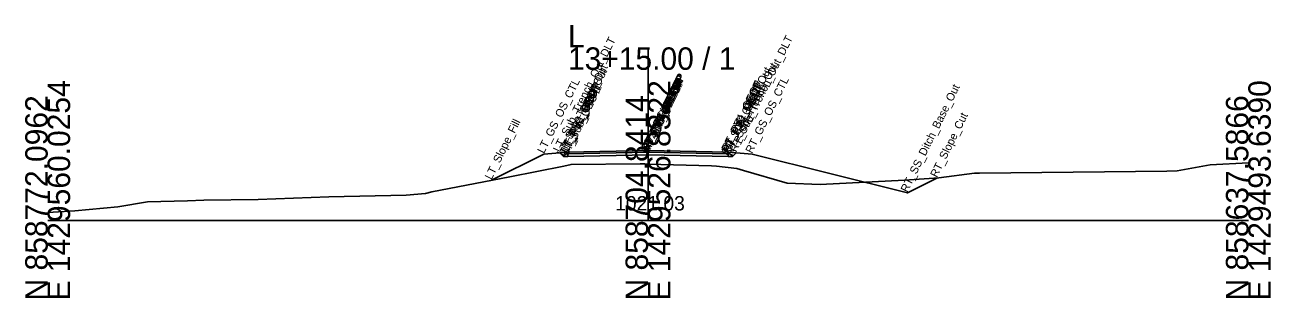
# Model space of a CAD drawing. Extents: x -26 to 2303, y -10 to 19558.
# Drawn here: x 1147.2 to 1302.8, y 7490.3 to 7524.4 of the extents above; entities that cross this region are included whole.
import ezdxf

# ---------------------------------------------------------------- set-up
doc = ezdxf.new("R2010")
doc.units = 0
for name, color, linetype in [('Default', 7, 'Continuous'), ('Exist Cross Section Cell', 7, 'Continuous'), ('Exist XS Center Line Elevation Label', 7, 'Continuous'), ('Exist XS Ground Line', 7, 'Continuous'), ('Prop CMT Pvmt Course 1', 7, 'Continuous'), ('Prop CMT Pvmt Course 2', 7, 'Continuous'), ('Prop CMT Pvmt Surface', 7, 'Continuous'), ('Prop CMT Pvmt Surface Shoulder', 7, 'Continuous'), ('Prop CMT Shld Paved Course 1', 7, 'Continuous'), ('Prop CMT Shld Paved Course 2', 7, 'Continuous'), ('Prop CMT Slope Grass', 7, 'Continuous'), ('Prop CMT Subgrade Earthwork', 7, 'Continuous'), ('Prop XS Dump Level', 7, 'Continuous')]:
    doc.layers.add(name, color=color, linetype=linetype)

msp = doc.modelspace()

# ---------------------------------------------------------------- linework, layer by layer
at = {"layer": 'Exist Cross Section Cell'}
for p, q in [((1225, 7500), (1225, 7521.58)), ((1150, 7500), (1225, 7500)), ((1225, 7500), (1300, 7500))]:
    msp.add_line(p, q, dxfattribs=at)
at = {"layer": 'Exist XS Ground Line'}
msp.add_lwpolyline([(1150, 7500.96), (1153.38, 7501.19), (1158.76, 7501.67), (1162.46, 7502.3), (1167.47, 7502.44), (1169.52, 7502.52), (1176.3, 7502.61), (1185.13, 7502.92), (1194.8, 7503.16), (1197.2, 7503.35), (1197.98, 7503.55), (1207.74, 7505.44), (1214.48, 7506.78), (1215.4, 7506.98), (1224, 7507.04), (1224.59, 7507.04), (1225, 7507.03), (1232.94, 7506.79), (1233.56, 7506.77), (1236.1, 7506.46), (1236.91, 7506.21), (1242.39, 7504.66), (1246.49, 7504.49), (1257.06, 7505.03), (1261.34, 7505.29), (1265.79, 7505.87), (1266.41, 7505.87), (1289.83, 7506.12), (1291.12, 7506.19), (1295.25, 7506.91), (1300, 7507.19)], dxfattribs=at)
at = {"layer": 'Prop CMT Pvmt Course 1'}
for points in [[(1225, 7508.71), (1215, 7508.51)], [(1225, 7508.5), (1225, 7508.71)], [(1225, 7508.71), (1235, 7508.51)], [(1225, 7508.5), (1225, 7508.71)], [(1215, 7508.51), (1215, 7508.3)], [(1215, 7508.3), (1225, 7508.5)], [(1235, 7508.3), (1225, 7508.5)], [(1235, 7508.51), (1235, 7508.3)]]:
    msp.add_lwpolyline(points, dxfattribs=at)
msp.add_lwpolyline([(1225, 7508.5), (1225, 7508.59), (1225, 7508.59), (1225, 7508.5)], close=True, dxfattribs=at)
msp.add_lwpolyline([(1225, 7508.5), (1225, 7508.59), (1225, 7508.59), (1225, 7508.5)], close=True, dxfattribs=at)
at = {"layer": 'Prop CMT Pvmt Course 2'}
for points in [[(1225, 7508.5), (1215, 7508.3)], [(1215, 7508.3), (1215, 7507.97)], [(1215, 7507.97), (1225, 7508.17)], [(1225, 7508.17), (1225, 7508.5)], [(1225, 7508.17), (1225, 7508.5)], [(1225, 7508.5), (1235, 7508.3)], [(1235, 7507.97), (1225, 7508.17)], [(1235, 7508.3), (1235, 7507.97)]]:
    msp.add_lwpolyline(points, dxfattribs=at)
at = {"layer": 'Prop CMT Pvmt Surface'}
for points in [[(1225, 7508.71), (1215, 7508.51)], [(1225, 7508.71), (1235, 7508.51)]]:
    msp.add_lwpolyline(points, dxfattribs=at)
at = {"layer": 'Prop CMT Pvmt Surface Shoulder'}
for points in [[(1215, 7508.51), (1215, 7508.51)], [(1235, 7508.51), (1235, 7508.51)]]:
    msp.add_lwpolyline(points, dxfattribs=at)
at = {"layer": 'Prop CMT Shld Paved Course 1'}
for points in [[(1215, 7508.51), (1214.79, 7508.3)], [(1214.79, 7508.3), (1215, 7508.3)], [(1215, 7508.51), (1215, 7508.51)], [(1215, 7508.3), (1215, 7508.51)], [(1235, 7508.51), (1235, 7508.51)], [(1235, 7508.51), (1235.21, 7508.3)], [(1235, 7508.3), (1235, 7508.51)], [(1235.21, 7508.3), (1235, 7508.3)]]:
    msp.add_lwpolyline(points, dxfattribs=at)
at = {"layer": 'Prop CMT Shld Paved Course 2'}
for points in [[(1214.79, 7508.3), (1214.45, 7507.96)], [(1214.45, 7507.96), (1215, 7507.97)], [(1215, 7508.3), (1214.79, 7508.3)], [(1214.79, 7508.3), (1214.79, 7508.3)], [(1215, 7507.97), (1215, 7508.3)], [(1235, 7508.3), (1235.21, 7508.3)], [(1235, 7507.97), (1235, 7508.3)], [(1235.55, 7507.96), (1235, 7507.97)], [(1235.21, 7508.3), (1235.21, 7508.3)], [(1235.21, 7508.3), (1235.55, 7507.96)]]:
    msp.add_lwpolyline(points, dxfattribs=at)
at = {"layer": 'Prop CMT Slope Grass'}
for points in [[(1215, 7508.51), (1212, 7508.27), (1205.45, 7505)], [(1235, 7508.51), (1238, 7508.27), (1257.4, 7503.42), (1261.09, 7505.27)]]:
    msp.add_lwpolyline(points, dxfattribs=at)
at = {"layer": 'Prop CMT Subgrade Earthwork'}
for points in [[(1214.45, 7507.96), (1213.98, 7508.43)], [(1215, 7507.97), (1214.45, 7507.96)], [(1225, 7508.17), (1215, 7507.97)], [(1225, 7508.17), (1235, 7507.97)], [(1235, 7507.97), (1235.55, 7507.96)], [(1235.55, 7507.96), (1236.02, 7508.43)]]:
    msp.add_lwpolyline(points, dxfattribs=at)

# ---------------------------------------------------------------- texts
at = {"layer": 'Default'}
msp.add_text('-', height=0.0001, dxfattribs=at).set_placement((1150, 7500))
at = {"layer": 'Exist Cross Section Cell'}
for s, p in [('L', (1215, 7521.58)), ('13+15.00 / 1', (1215, 7518.78))]:
    msp.add_text(s, height=2.8, dxfattribs=at).set_placement(p)
for s, p in [('E 1429560.0254', (1152.8, 7490)), ('E 1429526.8322', (1227.8, 7490)), ('E 1429493.6390', (1302.8, 7490)), ('N 858772.0962', (1150, 7490)), ('N 858704.8414', (1225, 7490)), ('N 858637.5866', (1300, 7490))]:
    msp.add_text(s, height=2.8, rotation=90, dxfattribs=at).set_placement(p)
at = {"layer": 'Exist XS Center Line Elevation Label'}
msp.add_text('1021.03', height=1.8, dxfattribs=at).set_placement((1220.9, 7501.23))
at = {"layer": 'Prop XS Dump Level'}
for s, p in [('LT_Sub_Trench_Out_DLT', (1213.98, 7508.43)), ('RT_Sub_Trench_Out_DLT', (1236.02, 7508.43)), ('LT_Sub_Trench_Out', (1214.45, 7507.96)), ('RT_Sub_Trench_Out', (1235.55, 7507.96)), ('LT_PS2_Shelf_Out', (1214.79, 7508.3)), ('RT_PV1_OEEOP', (1225, 7508.59)), ('RT_PV2_OEEOP', (1225, 7508.5)), ('LT_PV1_OEEOP', (1225, 7508.59)), ('LT_PV2_OEEOP', (1225, 7508.5)), ('RT_PS2_Shelf_Out', (1235.21, 7508.3)), ('LT_GS_OS_CTL', (1212, 7508.27)), ('LT_PS2_OEOP', (1214.79, 7508.3)), ('LT_PV1_OEOT', (1215, 7508.51)), ('LT_PS1_OEOP', (1215, 7508.51)), ('LT_PV2_OEOT', (1215, 7508.3)), ('LT_Sub_OEOT', (1215, 7507.97)), ('RT_Sub_OEEOP', (1225, 7508.17)), ('RT_PV1_IEEOP', (1225, 7508.59)), ('RT_PV2_IEEOP', (1225, 7508.5)), ('LT_Sub_OEEOP', (1225, 7508.17)), ('LT_PV1_IEEOP', (1225, 7508.59)), ('LT_PV2_IEEOP', (1225, 7508.5)), ('RT_PV1_OEOT', (1235, 7508.51)), ('RT_PS1_OEOP', (1235, 7508.51)), ('RT_PV2_OEOT', (1235, 7508.3)), ('RT_Sub_OEOT', (1235, 7507.97)), ('RT_PS2_OEOP', (1235.21, 7508.3)), ('RT_GS_OS_CTL', (1238, 7508.27)), ('RT_SS_Ditch_Base_Out', (1257.4, 7503.42)), ('PV1_PGL', (1225, 7508.71)), ('PV2_PGL', (1225, 7508.5)), ('RT_Slope_Cut', (1261.09, 7505.27)), ('LT_Slope_Fill', (1205.45, 7505))]:
    msp.add_text(s, height=1, rotation=63.5833, dxfattribs=at).set_placement(p)

doc.saveas('drawing.dxf')
